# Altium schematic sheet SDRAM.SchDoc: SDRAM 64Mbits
size A4; Date: Not used; ApprovedBy: Not used; CheckedBy: Not used; Author: Not used; CompanyName: STMicroelectronics; DrawnBy: Not used; Engineer: Not used; Organization: Not used; Address1: Not used; Address2: Not used; Address3: Not used; Address4: Not used; Revision: Not used; SheetNumber: 4; SheetTotal: 8
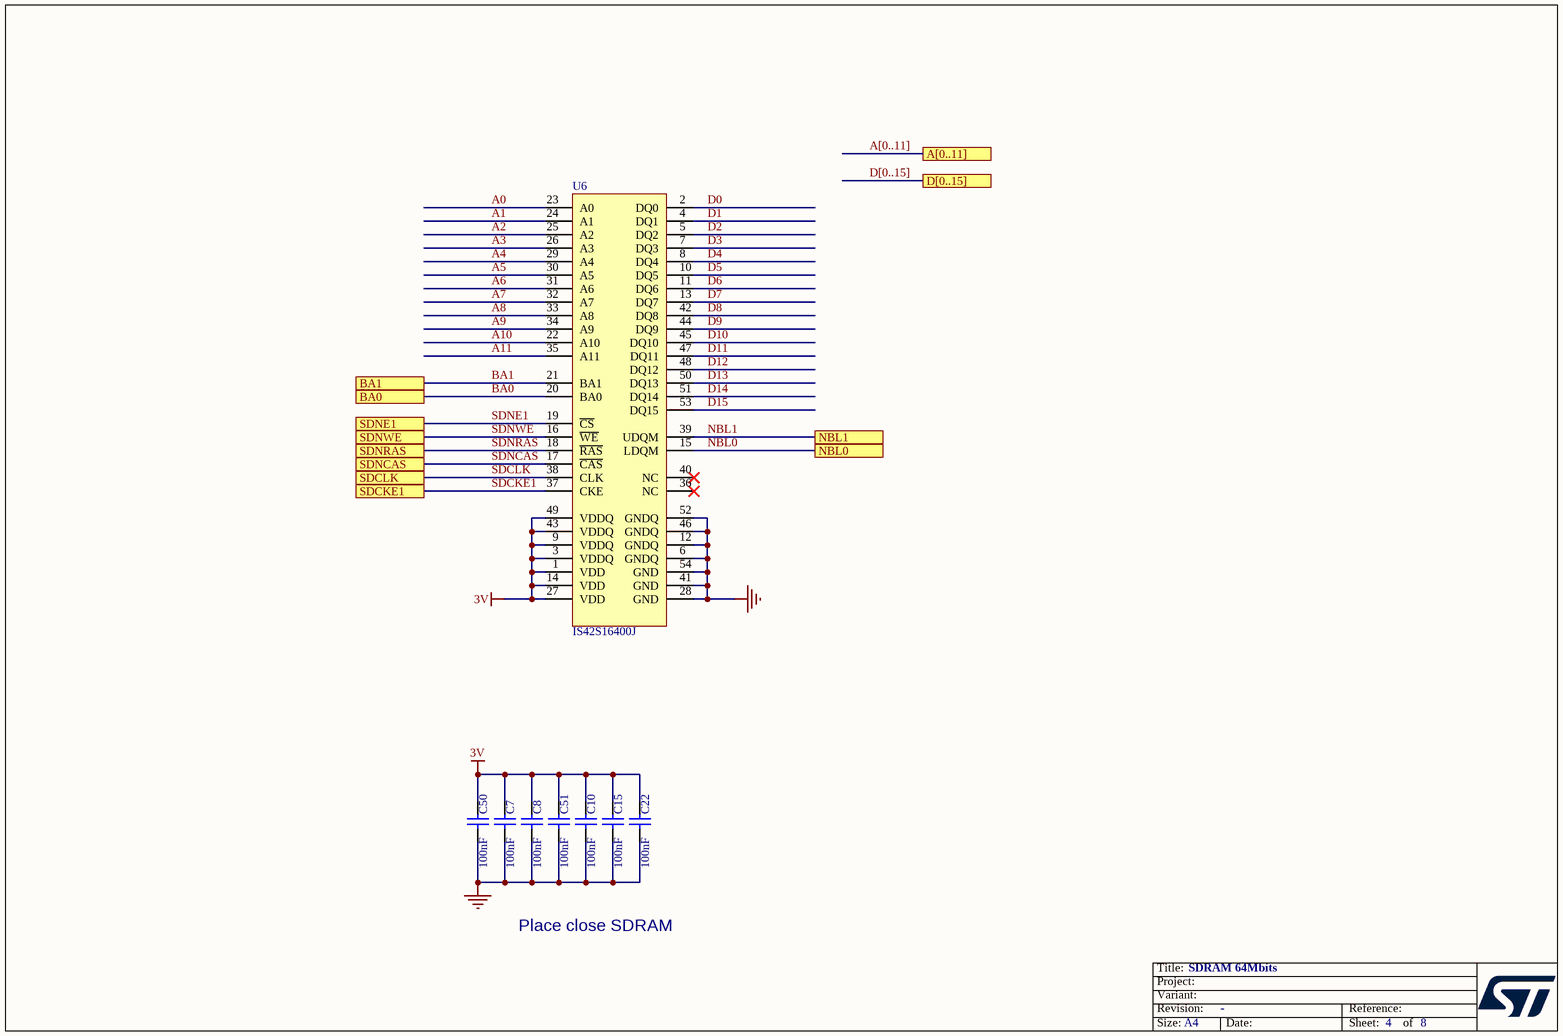
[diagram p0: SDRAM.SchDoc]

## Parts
C7  100nF  [0402C]
C8  100nF  [0402C]
C10  100nF  [0402C]
C15  100nF  [0402C]
C22  100nF  [0402C]
C50  100nF  [0402C]
C51  100nF  [0402C]
U6  IS42S16400J  [TSOP54-II]

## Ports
A[0..11], BA0, BA1, D[0..15], NBL0, NBL1, SDCKE1, SDCLK, SDNCAS, SDNE1, SDNRAS, SDNWE

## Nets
3V: C7.2 C8.2 C10.2 C15.2 C22.2 C50.2 C51.2 U6.1(VDD) U6.3(VDDQ) U6.9(VDDQ) U6.14(VDD) U6.27(VDD) U6.43(VDDQ) U6.49(VDDQ)
GND: C7.1 C8.1 C10.1 C15.1 C22.1 C50.1 C51.1 U6.6(GNDQ) U6.12(GNDQ) U6.28(GND) U6.41(GND) U6.46(GNDQ) U6.52(GNDQ) U6.54(GND)
A0: U6.23(A0)
A1: U6.24(A1)
A2: U6.25(A2)
A3: U6.26(A3)
A4: U6.29(A4)
A5: U6.30(A5)
A6: U6.31(A6)
A7: U6.32(A7)
A8: U6.33(A8)
A9: U6.34(A9)
A10: U6.22(A10)
A11: U6.35(A11)
BA0: U6.20(BA0) ; port BA0
BA1: U6.21(BA1) ; port BA1
D0: U6.2(DQ0)
D1: U6.4(DQ1)
D2: U6.5(DQ2)
D3: U6.7(DQ3)
D4: U6.8(DQ4)
D5: U6.10(DQ5)
D6: U6.11(DQ6)
D7: U6.13(DQ7)
D8: U6.42(DQ8)
D9: U6.44(DQ9)
D10: U6.45(DQ10)
D11: U6.47(DQ11)
D12: U6.48(DQ12)
D13: U6.50(DQ13)
D14: U6.51(DQ14)
D15: U6.53(DQ15)
NBL0: U6.15(LDQM) ; port NBL0
NBL1: U6.39(UDQM) ; port NBL1
SDCKE1: U6.37(CKE) ; port SDCKE1
SDCLK: U6.38(CLK) ; port SDCLK
SDNCAS: U6.17(~{CAS}) ; port SDNCAS
SDNE1: U6.19(~{CS}) ; port SDNE1
SDNRAS: U6.18(~{RAS}) ; port SDNRAS
SDNWE: U6.16(~{WE}) ; port SDNWE

Not connected (* = marked no-connect by the designer): U6 36(NC)* 40(NC)*

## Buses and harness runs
bus A[0..11] = port A[0..11]
bus D[0..15] = port D[0..15]

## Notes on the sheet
- Place close SDRAM

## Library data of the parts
C7 C8 C10 C15 C22 C50 C51 = Capacitor_ST: Capacitor 0402 / 0603 / 0805
U6 = IS45S16400J: SYNCHRONOUS DYNAMIC RAM, 1 Meg Bits x 16 Bits x 4 Banks (64-MBIT); Manuf_1: ISSI; Order: IS42S16400J-7TL; ECCN_US/EU: EAR99/NEC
